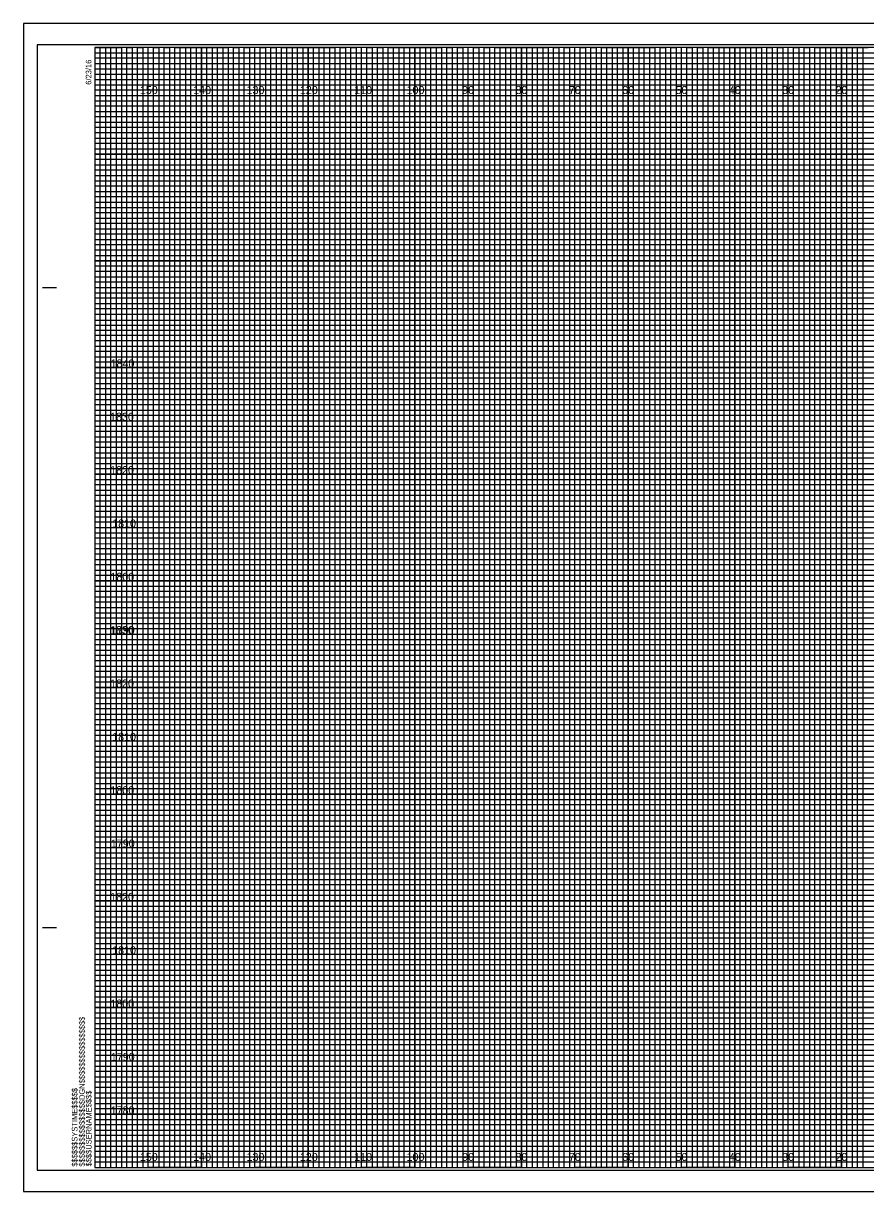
# Model space of a CAD drawing. Extents: x -13 to 323, y -5 to 874.
# Drawn here: x -13.4 to 144.5, y 435.5 to 654.5 of the extents above; entities that cross this region are included whole.
import ezdxf

# ---------------------------------------------------------------- set-up
doc = ezdxf.new("R2010")
doc.units = 0
for name, color, linetype in [('Prop XS Earthwork Shape', 7, 'Continuous'), ('Raster_Level_0', 7, 'Continuous'), ('Scratch_Level_3', 7, 'Continuous'), ('Sheet Cross Section CELL', 7, 'Continuous'), ('Sheet Cross Section Grid Middle CELL', 7, 'Continuous'), ('Sheet Cross Section Grid Minor 1 CELL', 7, 'Continuous'), ('Sheet Cross Section Grid Minor 2 CELL', 7, 'Continuous'), ('Sheet Cutting Line CELL', 7, 'Continuous'), ('Sheet DOT Grid CELL', 7, 'Continuous'), ('Sheet Plot Border Inside CELL', 7, 'Continuous'), ('Sheet Plot Border Outside CELL', 7, 'Continuous')]:
    doc.layers.add(name, color=color, linetype=linetype)

msp = doc.modelspace()

# ---------------------------------------------------------------- linework, layer by layer
at = {"layer": 'Prop XS Earthwork Shape'}
for p, q in [((10, 650), (0, 650)), ((10, 440), (10, 650)), ((30, 650), (20, 650)), ((20, 650), (20, 440)), ((30, 440), (30, 650)), ((50, 650), (40, 650)), ((40, 650), (40, 440)), ((50, 440), (50, 650)), ((70, 650), (60, 650)), ((60, 650), (60, 440)), ((70, 440), (70, 650)), ((90, 650), (80, 650)), ((80, 650), (80, 440)), ((90, 440), (90, 650)), ((110, 650), (100, 650)), ((100, 650), (100, 440)), ((110, 440), (110, 650)), ((130, 650), (120, 650)), ((120, 650), (120, 440)), ((130, 440), (130, 650)), ((150, 650), (140, 650)), ((140, 650), (140, 440)), ((20, 440), (10, 440)), ((40, 440), (30, 440)), ((60, 440), (50, 440)), ((80, 440), (70, 440)), ((100, 440), (90, 440)), ((120, 440), (110, 440)), ((140, 440), (130, 440))]:
    msp.add_line(p, q, dxfattribs=at)
for points in [[(0, 640), (320, 640), (320, 630), (0, 630)], [(0, 620), (320, 620), (320, 610), (0, 610)], [(0, 600), (320, 600), (320, 590), (0, 590)], [(0, 580), (320, 580), (320, 570), (0, 570)], [(0, 560), (320, 560), (320, 550), (0, 550)], [(0, 540), (320, 540), (320, 530), (0, 530)], [(0, 520), (320, 520), (320, 510), (0, 510)], [(0, 500), (320, 500), (320, 490), (0, 490)], [(0, 480), (320, 480), (320, 470), (0, 470)], [(0, 460), (320, 460), (320, 450), (0, 450)]]:
    msp.add_lwpolyline(points, dxfattribs=at)
at = {"layer": 'Sheet Cross Section CELL'}
for p, q in [((-9.8, 605), (-7.3, 605)), ((-9.7, 605), (-7.2, 605)), ((-9.8, 485), (-7.3, 485)), ((-9.7, 485), (-7.2, 485)), ((0, 440), (0, 440)), ((0, 440), (0, 440)), ((0, 440), (0, 440)), ((0, 440), (0, 440)), ((0, 440), (0, 440)), ((0, 440), (0, 440)), ((0, 440), (0, 440))]:
    msp.add_line(p, q, dxfattribs=at)
msp.add_lwpolyline([(320, 650), (0, 650), (0, 440), (320, 440)], close=True, dxfattribs=at)
at = {"layer": 'Sheet Cross Section Grid Middle CELL'}
for points in [[(0, 650), (5, 650), (5, 440), (15, 440), (15, 650), (25, 650), (25, 440), (35, 440), (35, 650), (45, 650), (45, 440), (55, 440), (55, 650), (65, 650), (65, 440), (75, 440), (75, 650), (85, 650), (85, 440), (95, 440), (95, 650), (105, 650), (105, 440), (115, 440), (115, 650), (125, 650), (125, 440), (135, 440), (135, 650), (145, 650)], [(0, 645), (275, 645)], [(0, 625), (320, 625), (320, 635), (0, 635)], [(0, 605), (320, 605), (320, 615), (0, 615)], [(0, 585), (320, 585), (320, 595), (0, 595)], [(0, 565), (320, 565), (320, 575), (0, 575)], [(0, 545), (320, 545), (320, 555), (0, 555)], [(0, 525), (320, 525), (320, 535), (0, 535)], [(0, 505), (320, 505), (320, 515), (0, 515)], [(0, 485), (320, 485), (320, 495), (0, 495)], [(0, 465), (320, 465), (320, 475), (0, 475)], [(0, 445), (320, 445), (320, 455), (0, 455)]]:
    msp.add_lwpolyline(points, dxfattribs=at)
at = {"layer": 'Sheet Cross Section Grid Minor 1 CELL'}
for p, q in [((0, 649), (260, 649)), ((260, 647.98), (0, 647.98)), ((0, 647.98), (0, 647)), ((0, 647), (260, 647)), ((260, 645.89), (0, 645.89)), ((0, 645.89), (0, 644)), ((0, 644), (320, 644))]:
    msp.add_line(p, q, dxfattribs=at)
for points in [[(0, 643), (270, 643), (320, 643), (320, 642), (0, 642)], [(0, 641), (320, 641), (320, 639), (0, 639)], [(0, 638), (320, 638), (320, 637), (0, 636.98)], [(0, 636), (320, 636), (320, 634), (0, 634)], [(0, 633), (320, 633), (320, 632), (0, 632)], [(0, 631), (320, 631), (320, 629), (0, 629)], [(0, 628), (320, 628), (320, 627), (0, 627)], [(0, 626), (320, 626), (320, 624), (0, 624)], [(0, 623), (320, 623), (320, 622), (0, 622)], [(0, 621), (320, 621), (320, 619), (0, 619)], [(0, 618), (320, 618), (320, 617), (0, 617)], [(0, 616), (320, 616), (320, 613.95), (320, 613), (320, 612), (0, 612)], [(0, 614), (320, 614), (320, 613), (0, 613)], [(0, 611), (320, 611), (320, 609), (0, 609.03)], [(0, 609.03), (320, 609), (320, 608), (0, 608)], [(0, 607), (320, 607), (320, 606), (0, 606)], [(0, 604), (320, 604), (320, 603), (0, 603)], [(0, 602), (320, 602), (320, 601), (0, 601)], [(-0.07, 598.89), (320, 598.89), (320, 597.88), (-0.07, 597.88)], [(0, 597), (320, 597), (320, 596), (0, 596)], [(0, 594), (320, 594), (320, 593), (0, 593)], [(0, 592), (320, 592), (320, 591), (0, 591)], [(0, 589), (320, 589), (320, 588), (0, 588)], [(0, 587), (320, 587), (320, 586), (0, 586)], [(0, 584), (320, 584), (320, 583), (0, 583)], [(0, 582), (320, 582), (320, 581), (0, 581)], [(0, 579), (320, 579), (319.99, 577.98), (0, 578)], [(0, 577), (320, 577), (320, 576), (0, 576)], [(0, 574), (320, 574), (320, 573), (0, 573)], [(0, 572), (320, 572), (320, 571), (0, 571)], [(0, 569), (320, 569), (320, 568), (0, 568)], [(0, 567), (320, 567), (320, 566), (0, 566)], [(0, 564), (320, 564), (320, 563), (0, 563)], [(0, 562), (320, 562), (320, 561), (0, 561)], [(0, 559), (320, 559), (320, 558), (0, 558)], [(0, 556.99), (320.07, 556.91), (320, 556), (0, 556)], [(0, 554), (320, 554), (320, 553), (0, 553)], [(0, 552), (320, 552), (320, 551), (0, 551)], [(0, 549), (320, 549), (320, 548), (0, 548)], [(0, 547), (320, 547), (320, 546), (0, 546)], [(0, 544), (320, 544), (320, 543), (0, 543)], [(0, 542), (320, 542), (320, 541), (0, 541)], [(0, 539), (320, 539), (320, 538), (0, 538)], [(0, 537), (320, 537), (320, 536), (0, 536)], [(0, 534), (320, 534), (320, 533), (0, 533)], [(0, 532), (320, 532), (320, 531), (0, 531)], [(0, 529), (320, 529), (320, 528), (0, 528)], [(0, 527), (320, 527), (320, 526), (0, 526)], [(0, 524), (320, 524), (320, 523), (0, 523)], [(0, 522), (320, 522), (320, 521), (0, 521)], [(0, 519), (320, 519), (319.99, 517.98), (0, 518)], [(0, 517), (320, 517), (320, 516), (0, 516)], [(0, 514), (320, 514), (320, 513), (0, 513)], [(0, 512), (320, 512), (320, 511), (0, 511)], [(0, 509), (320, 509), (320, 508), (0, 508)], [(0, 507), (320, 507), (320, 506), (0, 506)], [(0, 504), (320, 504), (320, 503), (0, 503)], [(0, 502), (320, 502), (320, 501), (0, 501)], [(0, 499), (320, 499), (320, 498), (0, 498)], [(0, 496.99), (320.07, 496.91), (320, 496), (0, 496)], [(0, 494), (320, 494), (320, 493), (0, 493)], [(0, 492), (320, 492), (320, 491), (0, 491)], [(0, 489), (320, 489), (320, 488), (0, 488)], [(0, 487), (320, 487), (320, 486), (0, 486)], [(0, 484), (320, 484), (320, 483), (0, 483)], [(0, 482), (320, 482), (320, 481), (0, 481)], [(0, 479), (320, 479), (320, 478), (0, 478)], [(0, 477), (320, 477), (320, 476), (0, 476)], [(0, 474), (320, 474), (320, 473), (0, 473)], [(0, 472), (320, 472), (320, 471), (0, 471)], [(0, 469), (320, 469), (320, 468), (0, 468)], [(0, 467), (320, 467), (320, 466), (0, 466)], [(0, 464), (320, 464), (320, 463), (0, 463)], [(0, 462), (320, 462), (320, 461), (0, 461)], [(0, 459), (320, 459), (320, 458), (0, 458)], [(0, 457), (320, 457), (320, 456), (0, 456)], [(0, 454), (320, 454), (320, 453), (0, 453)], [(0, 452), (320, 452), (320, 451), (0, 451)], [(0, 449), (320, 449), (320, 448), (0, 448)], [(0, 447), (320, 447), (320, 446), (0, 446)], [(0, 444), (320, 444), (320, 443), (0, 443)], [(0, 442), (320, 442), (320, 441), (0, 441)]]:
    msp.add_lwpolyline(points, dxfattribs=at)
at = {"layer": 'Sheet Cross Section Grid Minor 2 CELL'}
for points in [[(0, 440), (1, 440), (1, 650), (2, 650), (2, 440)], [(2, 440), (3, 440), (3, 650), (4, 650), (4, 440)], [(5, 440), (6, 440), (6, 650), (7, 650), (7, 440)], [(7, 440), (8, 440), (8, 650), (9, 650), (9, 440)], [(10, 440), (11, 440), (11, 650), (12, 650), (12, 440)], [(12, 440), (13, 440), (13, 650), (14, 650), (14, 440)], [(15, 440), (16, 440), (16, 650), (17, 650), (17, 440)], [(17, 440), (18, 440), (18, 650), (19, 650), (19, 440)], [(20, 440), (21, 440), (21, 650), (22, 650), (22, 440)], [(22, 440), (23, 440), (23, 650), (24, 650), (24, 440)], [(25, 440), (26, 440), (26, 650), (27, 650), (27, 440)], [(27, 440), (28, 440), (28, 650), (29, 650), (29, 440)], [(30, 440), (31, 440), (31, 650), (32, 650), (32, 440)], [(32, 440), (33, 440), (33, 650), (34, 650), (34, 440)], [(35, 440), (36, 440), (36, 650), (37, 650), (37, 440)], [(37, 440), (38, 440), (38, 650), (39, 650), (39, 440)], [(40, 440), (41, 440), (41, 650), (42, 650), (42, 440)], [(42, 440), (43, 440), (43, 650), (44, 650), (44, 440)], [(45, 440), (46, 440), (46, 650), (47, 650), (47, 440)], [(47, 440), (48, 440), (48, 650), (49, 650), (49, 440)], [(50, 440), (51, 440), (51, 650), (52, 650), (52, 440)], [(52, 440), (53, 440), (53, 650), (54, 650), (54, 440)], [(55, 440), (56, 440), (56, 650), (57, 650), (57, 440)], [(57, 440), (58, 440), (58, 650), (59, 650), (59, 440)], [(60, 440), (61, 440), (61, 650), (62, 650), (62, 440)], [(62, 440), (63, 440), (63, 650), (64, 650), (64, 440)], [(65, 440), (66, 440), (66, 650), (67, 650), (67, 440)], [(67, 440), (68, 440), (68, 650), (69, 650), (69, 440)], [(70, 440), (71, 440), (71, 650), (72, 650), (72, 440)], [(72, 440), (73, 440), (73, 650), (74, 650), (74, 440)], [(75, 440), (76, 440), (76, 650), (77, 650), (77, 440)], [(77, 440), (78, 440), (78, 650), (79, 650), (79, 440)], [(80, 440), (81, 440), (81, 650), (82, 650), (82, 440)], [(82, 440), (83, 440), (83, 650), (84, 650), (84, 440)], [(85, 440), (86, 440), (86, 650), (87, 650), (87, 440)], [(87, 440), (88, 440), (88, 650), (89, 650), (89, 440)], [(90, 440), (91, 440), (91, 650), (92, 650), (92, 440)], [(92, 440), (93, 440), (93, 650), (94, 650), (94, 440)], [(95, 440), (96, 440), (96, 650), (97, 650), (97, 440)], [(97, 440), (98, 440), (98, 650), (99, 650), (99, 440)], [(100, 440), (101, 440), (101, 650), (102, 650), (102, 440)], [(102, 440), (103, 440), (103, 650), (104, 650), (104, 440)], [(105, 440), (106, 440), (106, 650), (107, 650), (107, 440)], [(107, 440), (108, 440), (108, 650), (109, 650), (109, 440)], [(110, 440), (111, 440), (111, 650), (112, 650), (112, 440)], [(112, 440), (113, 440), (113, 650), (114, 650), (114, 440)], [(115, 440), (116, 440), (116, 650), (117, 650), (117, 440)], [(117, 440), (118, 440), (118, 650), (119, 650), (119, 440)], [(120, 440), (121, 440), (121, 650), (122, 650), (122, 440)], [(122, 440), (123, 440), (123, 650), (124, 650), (124, 440)], [(125, 440), (126, 440), (126, 650), (127, 650), (127, 440)], [(127, 440), (128, 440), (128, 650), (129, 650), (129, 440)], [(130, 440), (131, 440), (131, 650), (132, 650), (132, 440)], [(132, 440), (133, 440), (133, 650), (134, 650), (134, 440)], [(135, 440), (136, 440), (136, 650), (137, 650), (137, 440)], [(137, 440), (138, 440), (138, 650), (139, 650), (139, 440)], [(140, 440), (141, 440), (141, 650), (142, 650), (142, 440)], [(142, 440), (143, 440), (143, 650), (144, 650), (144, 440)]]:
    msp.add_lwpolyline(points, dxfattribs=at)
at = {"layer": 'Sheet Cutting Line CELL'}
for p, q in [((323.3, 654.5), (-13.4, 654.5)), ((-13.4, 654.5), (-13.4, 435.5)), ((-13.4, 435.5), (323.3, 435.5))]:
    msp.add_line(p, q, dxfattribs=at)
at = {"layer": 'Sheet DOT Grid CELL'}
for p, q in [((10, 440), (10, 650)), ((20, 440), (20, 650)), ((30, 440), (30, 650)), ((40, 440), (40, 650)), ((50, 440), (50, 650)), ((60, 440), (60, 650)), ((70, 440), (70, 650)), ((80, 440), (80, 650)), ((90, 440), (90, 650)), ((100, 440), (100, 650)), ((110, 440), (110, 650)), ((120, 440), (120, 650)), ((130, 440), (130, 650)), ((140, 440), (140, 650)), ((0, 640), (320, 640)), ((0, 630), (320, 630)), ((0, 620), (320, 620)), ((0, 610), (320, 610)), ((0, 600), (320, 600)), ((0, 590), (320, 590)), ((0, 580), (320, 580)), ((0, 570), (320, 570)), ((0, 560), (320, 560)), ((0, 550), (320, 550)), ((0, 540), (320, 540)), ((0, 530), (320, 530)), ((0, 520), (320, 520)), ((0, 510), (320, 510)), ((0, 500), (320, 500)), ((0, 490), (320, 490)), ((0, 480), (320, 480)), ((0, 470), (320, 470)), ((0, 460), (320, 460)), ((0, 450), (320, 450))]:
    msp.add_line(p, q, dxfattribs=at)
at = {"layer": 'Sheet Plot Border Inside CELL'}
msp.add_lwpolyline([(-10.8, 439.5), (322.4, 439.5), (322.4, 650.5), (-10.8, 650.5)], close=True, dxfattribs=at)
at = {"layer": 'Sheet Plot Border Outside CELL'}
msp.add_lwpolyline([(-13.4, 435.5), (323.3, 435.5), (323.3, 654.5), (-13.4, 654.5)], close=True, dxfattribs=at)

# ---------------------------------------------------------------- texts
at = {"layer": 'Raster_Level_0'}
for s, p in [('150', (8.44, 641.25)), ('140', (18.44, 641.25)), ('130', (28.44, 641.25)), ('120', (38.44, 641.25)), ('110', (48.62, 641.25)), ('100', (58.44, 641.25)), ('90', (68.86, 641.25)), ('80', (78.86, 641.25)), ('70', (88.86, 641.25)), ('60', (98.86, 641.25)), ('50', (108.86, 641.25)), ('40', (118.86, 641.25)), ('30', (128.86, 641.25)), ('20', (138.86, 641.25)), ('150', (8.44, 441.25)), ('140', (18.44, 441.25)), ('130', (28.44, 441.25)), ('120', (38.44, 441.25)), ('110', (48.62, 441.25)), ('100', (58.44, 441.25)), ('90', (68.86, 441.25)), ('80', (78.86, 441.25)), ('70', (88.86, 441.25)), ('60', (98.86, 441.25)), ('50', (108.86, 441.25)), ('40', (118.86, 441.25)), ('30', (128.86, 441.25)), ('20', (138.86, 441.25))]:
    msp.add_text(s, height=1.5, dxfattribs=at).set_placement(p)
at = {"layer": 'Scratch_Level_3'}
for s, p in [('1840', (2.95, 590)), ('1830', (2.86, 580)), ('1820', (2.87, 570)), ('1810', (3.25, 560)), ('1800', (2.92, 550)), ('1830', (2.86, 540)), ('1790', (3, 540)), ('1820', (2.87, 530)), ('1810', (3.25, 520)), ('1800', (2.92, 510)), ('1790', (3, 500)), ('1820', (2.87, 490)), ('1810', (3.25, 480)), ('1800', (2.92, 470)), ('1790', (3, 460)), ('1780', (2.98, 450))]:
    msp.add_text(s, height=1.5, dxfattribs=at).set_placement(p)
at = {"layer": 'Sheet Cross Section CELL'}
for s, p in [('6/23/16', (-0.65, 643)), ('$$$$$$$$$$$$$$$$DGN$$$$$$$$$$$$$$$$', (-1.88, 440.18)), ('$$$$$$SYSTIME$$$$$', (-3.26, 440.18)), ('$$$$USERNAME$$$$', (-0.62, 440.23))]:
    msp.add_text(s, height=1.05, rotation=90, dxfattribs=at).set_placement(p)

doc.saveas('drawing.dxf')
